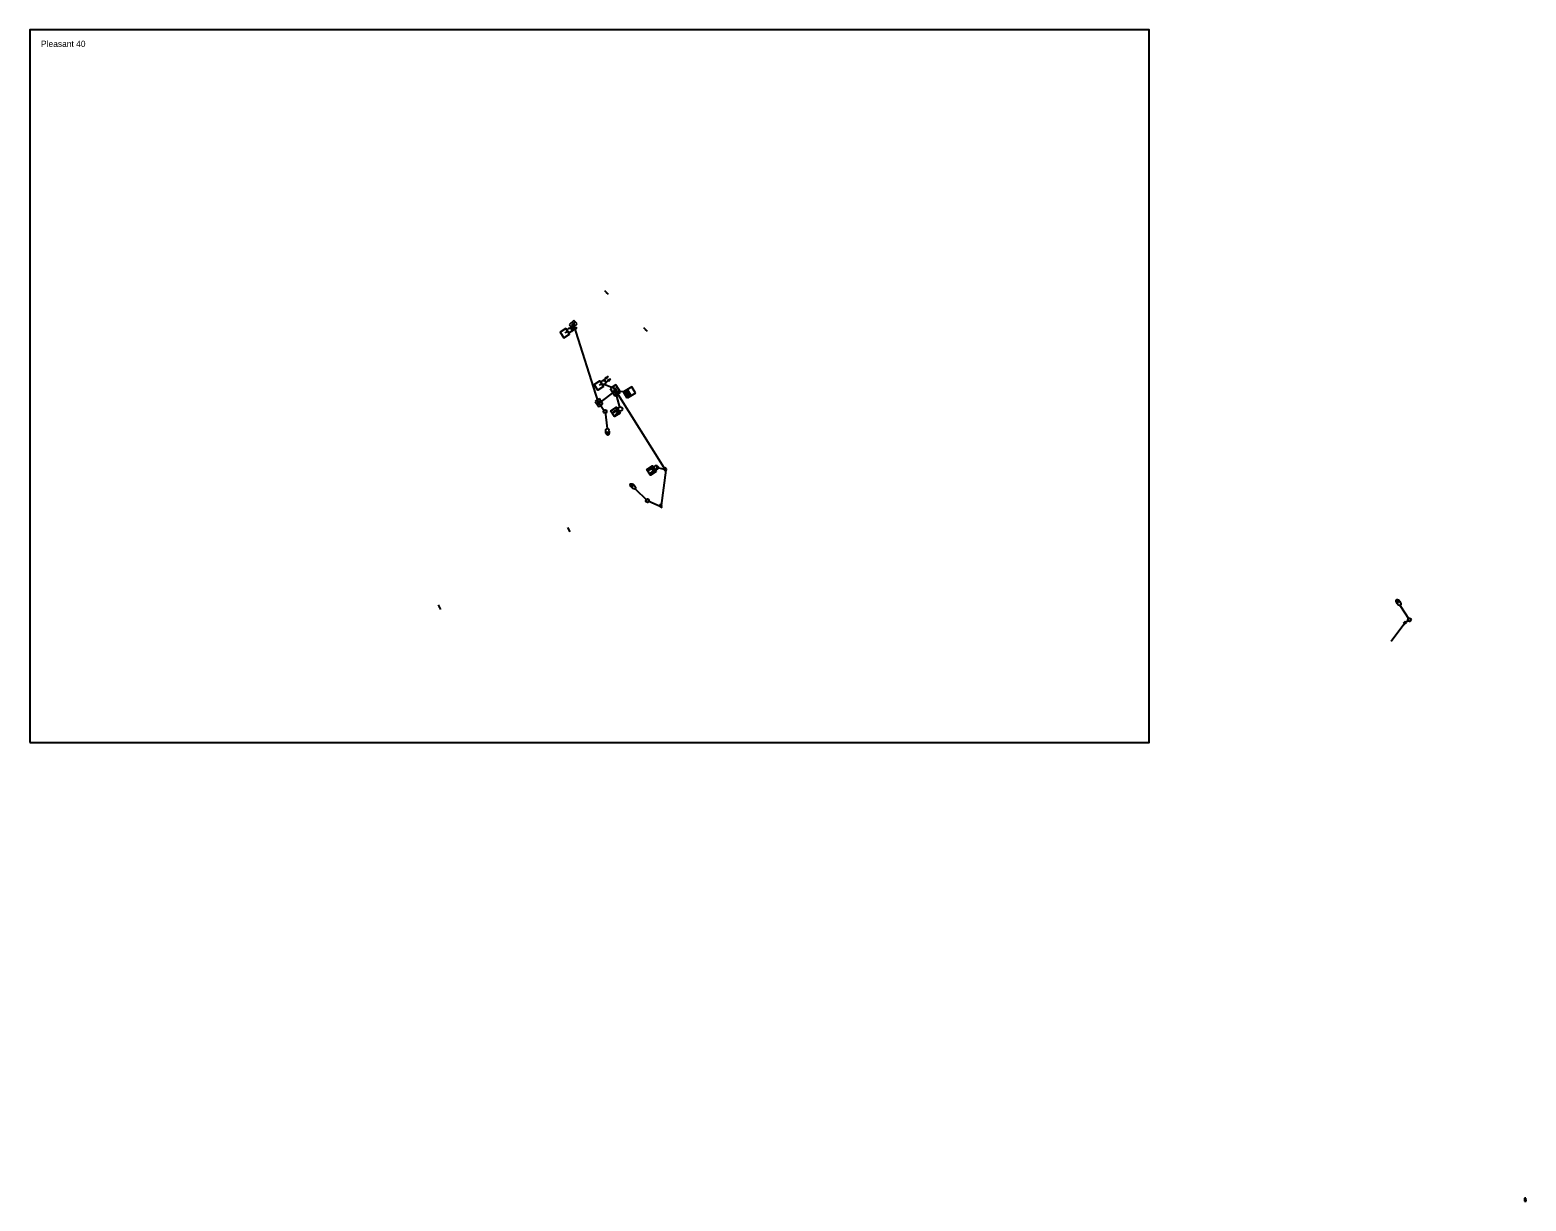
# Model space of a CAD drawing. Extents: x 995815 to 1000702, y 1981720 to 1984760.
# Drawn here: x 996829 to 997711, y 1982302 to 1982992 of the extents above; entities that cross this region are included whole.
import ezdxf

# ---------------------------------------------------------------- set-up
doc = ezdxf.new("R2010")
doc.units = 0
for name, color, linetype in [('DSN_Drain_Alignment_ArDOT_BMCD_Rt', 7, 'Continuous'), ('DSN_DRAIN_Analytics_ArDOT_BMCD_Rt', 7, 'Continuous'), ('DSN_DRFT_Common-Annotations', 7, 'Continuous'), ('DSN_DRFT_Const-No-Plot', 7, 'Continuous'), ('DSN_DRFT_Guideline-No-Plot', 7, 'Continuous'), ('DSN_DRFT_Junk-No-Plot', 7, 'Continuous'), ('DSN_RDWY_Alignment', 7, 'Continuous'), ('DSN_ROW_Point-Name-Annotation', 7, 'Continuous')]:
    doc.layers.add(name, color=color, linetype=linetype)

msp = doc.modelspace()

# ---------------------------------------------------------------- linework, layer by layer
at = {"layer": 'DSN_Drain_Alignment_ArDOT_BMCD_Rt'}
for centre in [(997168.24, 1982767.28), (997193.15, 1982714.71), (997642.44, 1982644.56)]:
    msp.add_circle(centre, 1, dxfattribs=at)
at = {"layer": 'DSN_DRAIN_Analytics_ArDOT_BMCD_Rt'}
for points in [[(997145.13, 1982816.17), (997141.75, 1982814.03), (997143.88, 1982810.65), (997147.27, 1982812.78)], [(997167.26, 1982782), (997163.88, 1982779.86), (997161.74, 1982783.24), (997165.12, 1982785.38)], [(997177.15, 1982766.38), (997173.77, 1982764.24), (997171.64, 1982767.62), (997175.02, 1982769.76)], [(997198.34, 1982731.9), (997194.96, 1982729.77), (997192.82, 1982733.15), (997196.2, 1982735.29)]]:
    msp.add_lwpolyline(points, close=True, dxfattribs=at)
at = {"layer": 'DSN_DRFT_Common-Annotations'}
for p, q in [((997149.71, 1982821), (997147.12, 1982818.29)), ((997151.82, 1982818.98), (997149.71, 1982821)), ((997145.32, 1982813.4), (997144.85, 1982814.14)), ((997146.2, 1982814.47), (997145.08, 1982813.77)), ((997147.12, 1982818.29), (997149.23, 1982816.27)), ((997148.53, 1982818.32), (997149.74, 1982819.59)), ((997149.74, 1982819.59), (997148.53, 1982818.32)), ((997149.2, 1982817.69), (997148.53, 1982818.32)), ((997148.53, 1982818.32), (997149.2, 1982817.69)), ((997149.2, 1982817.69), (997150.41, 1982818.95)), ((997149.2, 1982817.69), (997150.41, 1982818.95)), ((997149.23, 1982816.27), (997151.82, 1982818.98)), ((997150.41, 1982818.95), (997149.74, 1982819.59)), ((997150.41, 1982818.95), (997149.74, 1982819.59)), ((997164.84, 1982783.35), (997165.31, 1982782.62)), ((997166.19, 1982783.69), (997165.08, 1982782.99)), ((997174.57, 1982783.07), (997171.16, 1982780.91)), ((997171.16, 1982780.91), (997173.93, 1982776.53)), ((997174.17, 1982781.12), (997173.09, 1982780.45)), ((997173.09, 1982780.45), (997174.34, 1982778.47)), ((997173.93, 1982776.53), (997177.34, 1982778.69)), ((997175.41, 1982779.15), (997174.17, 1982781.12)), ((997174.34, 1982778.47), (997175.41, 1982779.15)), ((997177.34, 1982778.69), (997174.57, 1982783.07)), ((997164.9, 1982774.71), (997162.43, 1982773.15)), ((997162.43, 1982773.15), (997164.43, 1982769.98)), ((997164.59, 1982773.33), (997163.81, 1982772.83)), ((997164.59, 1982773.33), (997163.81, 1982772.83)), ((997164.74, 1982771.35), (997163.81, 1982772.83)), ((997163.81, 1982772.83), (997164.74, 1982771.35)), ((997164.43, 1982769.98), (997166.9, 1982771.53)), ((997165.52, 1982771.85), (997164.59, 1982773.33)), ((997165.52, 1982771.85), (997164.59, 1982773.33)), ((997165.52, 1982771.85), (997164.74, 1982771.35)), ((997164.74, 1982771.35), (997165.52, 1982771.85)), ((997166.9, 1982771.53), (997164.9, 1982774.71)), ((997176.09, 1982768.07), (997174.97, 1982767.37)), ((997174.74, 1982767.73), (997175.2, 1982767)), ((997195.92, 1982733.26), (997196.39, 1982732.52)), ((997197.27, 1982733.59), (997196.15, 1982732.89)), ((997203.46, 1982734.27), (997202.74, 1982733.7)), ((997202.74, 1982733.7), (997203.83, 1982732.33)), ((997204.55, 1982732.9), (997203.46, 1982734.27)), ((997203.83, 1982732.33), (997204.55, 1982732.9)), ((997200.97, 1982712.59), (997200.2, 1982712.09)), ((997200.2, 1982712.09), (997201.14, 1982710.62)), ((997201.92, 1982711.11), (997200.97, 1982712.59)), ((997201.14, 1982710.62), (997201.92, 1982711.11)), ((997640.02, 1982643.58), (997638.81, 1982642.32)), ((997638.81, 1982642.32), (997639.47, 1982641.68)), ((997639.47, 1982641.68), (997640.68, 1982642.95)), ((997640.68, 1982642.95), (997640.02, 1982643.58)), ((997711.2, 1982303.71), (997710.28, 1982303.68)), ((997710.28, 1982303.68), (997710.34, 1982301.93)), ((997710.34, 1982301.93), (997711.26, 1982301.96)), ((997711.26, 1982301.96), (997711.2, 1982303.71))]:
    msp.add_line(p, q, dxfattribs=at)
at = {"layer": 'DSN_DRFT_Const-No-Plot'}
for p, q in [((997183.94, 1982781.85), (997178.99, 1982778.94)), ((997181.18, 1982775.21), (997178.99, 1982778.94)), ((997181.24, 1982779.88), (997179.44, 1982778.82)), ((997181.3, 1982775.66), (997179.44, 1982778.82)), ((997179.44, 1982778.82), (997183.09, 1982776.71)), ((997186.13, 1982778.11), (997181.18, 1982775.21)), ((997183.09, 1982776.71), (997181.24, 1982779.88)), ((997181.29, 1982775.68), (997181.24, 1982779.88)), ((997183.55, 1982776.59), (997181.35, 1982780.33)), ((997186.13, 1982778.11), (997183.94, 1982781.85)), ((997183.09, 1982776.71), (997181.3, 1982775.66))]:
    msp.add_line(p, q, dxfattribs=at)
at = {"layer": 'DSN_DRFT_Guideline-No-Plot'}
for p, q in [((997168.24, 1982767.28), (997169.36, 1982757.34)), ((997193.15, 1982714.71), (997186.04, 1982721.75)), ((997642.44, 1982644.56), (997637.1, 1982653.01))]:
    msp.add_line(p, q, dxfattribs=at)
for centre, major_axis in [((997169.58, 1982755.35), (0.22, -1.99)), ((997169.69, 1982754.36), (-0.112, 0.994)), ((997184.62, 1982723.15), (-1.42, 1.41)), ((997183.91, 1982723.86), (0.711, -0.703)), ((997636.03, 1982654.7), (-1.07, 1.69)), ((997635.5, 1982655.55), (0.534, -0.846))]:
    msp.add_ellipse(centre, major_axis=major_axis, ratio=0.5, dxfattribs=at)
at = {"layer": 'DSN_DRFT_Junk-No-Plot'}
msp.add_lwpolyline([(996829.08, 1982572.16), (997489.08, 1982572.16), (997489.08, 1982992.16), (996829.08, 1982992.16)], close=True, dxfattribs=at)
at = {"layer": 'DSN_RDWY_Alignment'}
for p, q in [((997148.86, 1982818), (997148.13, 1982816.04)), ((997164.2, 1982773.08), (997149.8, 1982818.32)), ((997173.87, 1982779.21), (997165.06, 1982772.59)), ((997173.63, 1982780.79), (997167.66, 1982783.17)), ((997174.34, 1982778.47), (997176.74, 1982769.92)), ((997203.1, 1982733.99), (997174.87, 1982778.81)), ((997178.99, 1982778.94), (997175.41, 1982779.15)), ((997165.13, 1982771.6), (997167.53, 1982767.99)), ((997203.28, 1982733.02), (997198.33, 1982734.26)), ((997201.45, 1982711.85), (997204.19, 1982732.62)), ((997200.67, 1982711.35), (997194.06, 1982714.3)), ((997631.65, 1982631.82), (997639.14, 1982642)), ((997640.35, 1982643.27), (997641.73, 1982643.85))]:
    msp.add_line(p, q, dxfattribs=at)
at = {"layer": 'DSN_ROW_Point-Name-Annotation'}
for p, q in [((997170.27, 1982836.28), (997168.07, 1982838.32)), ((997168.91, 1982837.2), (997169.08, 1982837.38)), ((997168.91, 1982837.2), (997169.09, 1982837.03)), ((997169.26, 1982837.21), (997169.08, 1982837.38)), ((997169.26, 1982837.21), (997169.09, 1982837.03)), ((997147.72, 1982817.22), (997149.32, 1982814.68)), ((997147.98, 1982816.8), (997150.54, 1982818.41)), ((997148.31, 1982815.82), (997148.52, 1982815.95)), ((997149.05, 1982815.11), (997151.6, 1982816.72)), ((997193.18, 1982814.45), (997190.98, 1982816.5)), ((997191.82, 1982815.38), (997191.99, 1982815.56)), ((997191.82, 1982815.38), (997192, 1982815.21)), ((997192.17, 1982815.39), (997191.99, 1982815.56)), ((997192.17, 1982815.39), (997192, 1982815.21)), ((997169.48, 1982784.16), (997167.42, 1982786.34)), ((997167.77, 1982785.97), (997169.96, 1982788.05)), ((997169.14, 1982784.52), (997171.33, 1982786.6)), ((997168.27, 1982785.08), (997168.45, 1982785.25)), ((997175.21, 1982768.6), (997173.05, 1982766.49)), ((997174.86, 1982768.96), (997176.96, 1982766.82)), ((997176.09, 1982768.06), (997175.91, 1982767.89)), ((997176.61, 1982767.18), (997174.45, 1982765.06)), ((997196.52, 1982734.31), (997193.97, 1982732.7)), ((997196.26, 1982734.73), (997197.86, 1982732.19)), ((997197.27, 1982733.59), (997197.06, 1982733.46)), ((997197.59, 1982732.62), (997195.04, 1982731.01)), ((997146, 1982698.92), (997147.4, 1982696.27)), ((997146.64, 1982697.71), (997146.86, 1982697.82)), ((997146.64, 1982697.71), (997146.76, 1982697.48)), ((997146.98, 1982697.6), (997146.76, 1982697.48)), ((997146.98, 1982697.6), (997146.86, 1982697.82)), ((997069.71, 1982653.24), (997071.11, 1982650.59)), ((997070.35, 1982652.02), (997070.57, 1982652.14)), ((997070.35, 1982652.02), (997070.47, 1982651.8)), ((997070.69, 1982651.92), (997070.47, 1982651.8)), ((997070.69, 1982651.92), (997070.57, 1982652.14))]:
    msp.add_line(p, q, dxfattribs=at)
for centre in [(997147.25, 1982815.15), (997167.25, 1982784.36), (997177.14, 1982768.73), (997198.33, 1982734.26)]:
    msp.add_circle(centre, 1.25, dxfattribs=at)
for centre, radius, start, end in [((997144.62, 1982831.91), 14.74, 285.92296, 293.66107), ((997148.31, 1982817.01), 0.814, 0.42207, 64.11671), ((997160.18, 1982807.27), 14.74, 130.8777, 138.61582), ((997145.69, 1982830.22), 14.74, 285.92296, 293.66107), ((997149.38, 1982815.31), 0.814, 0.42207, 64.11671), ((997161.25, 1982805.58), 14.74, 130.8777, 138.61582), ((997161.54, 1982800.14), 14.74, 297.1178, 304.85591), ((997168.05, 1982786.24), 0.814, 11.61691, 75.31155), ((997181.58, 1982778.99), 14.74, 142.07255, 149.81066), ((997162.91, 1982798.69), 14.74, 297.1178, 304.85591), ((997182.96, 1982777.54), 14.74, 142.07255, 149.81066), ((997169.42, 1982784.79), 0.814, 11.61691, 75.31155), ((997161.27, 1982775.34), 14.74, 323.08968, 330.82779), ((997174.93, 1982768.33), 0.814, 192.63404, 256.32868), ((997181.69, 1982754.55), 14.74, 118.13493, 125.87305), ((997162.67, 1982773.91), 14.74, 323.08968, 330.82779), ((997183.09, 1982753.12), 14.74, 118.13493, 125.87305), ((997176.33, 1982766.91), 0.814, 192.63404, 256.32868), ((997184.32, 1982743.83), 14.74, 310.90529, 318.64341), ((997199.89, 1982719.2), 14.74, 105.95054, 113.68866), ((997196.19, 1982734.1), 0.814, 180.44966, 244.14429), ((997185.39, 1982742.14), 14.74, 310.90529, 318.64341), ((997200.96, 1982717.51), 14.74, 105.95054, 113.68866), ((997197.26, 1982732.41), 0.814, 180.44966, 244.14429)]:
    msp.add_arc(centre, radius, start, end, dxfattribs=at)

# ---------------------------------------------------------------- texts
at = {"layer": 'DSN_DRFT_Junk-No-Plot'}
msp.add_text('Pleasant 40', height=3.72, rotation=359.97484, dxfattribs=at).set_placement((996835.6, 1982982.12))

doc.saveas('drawing.dxf')
